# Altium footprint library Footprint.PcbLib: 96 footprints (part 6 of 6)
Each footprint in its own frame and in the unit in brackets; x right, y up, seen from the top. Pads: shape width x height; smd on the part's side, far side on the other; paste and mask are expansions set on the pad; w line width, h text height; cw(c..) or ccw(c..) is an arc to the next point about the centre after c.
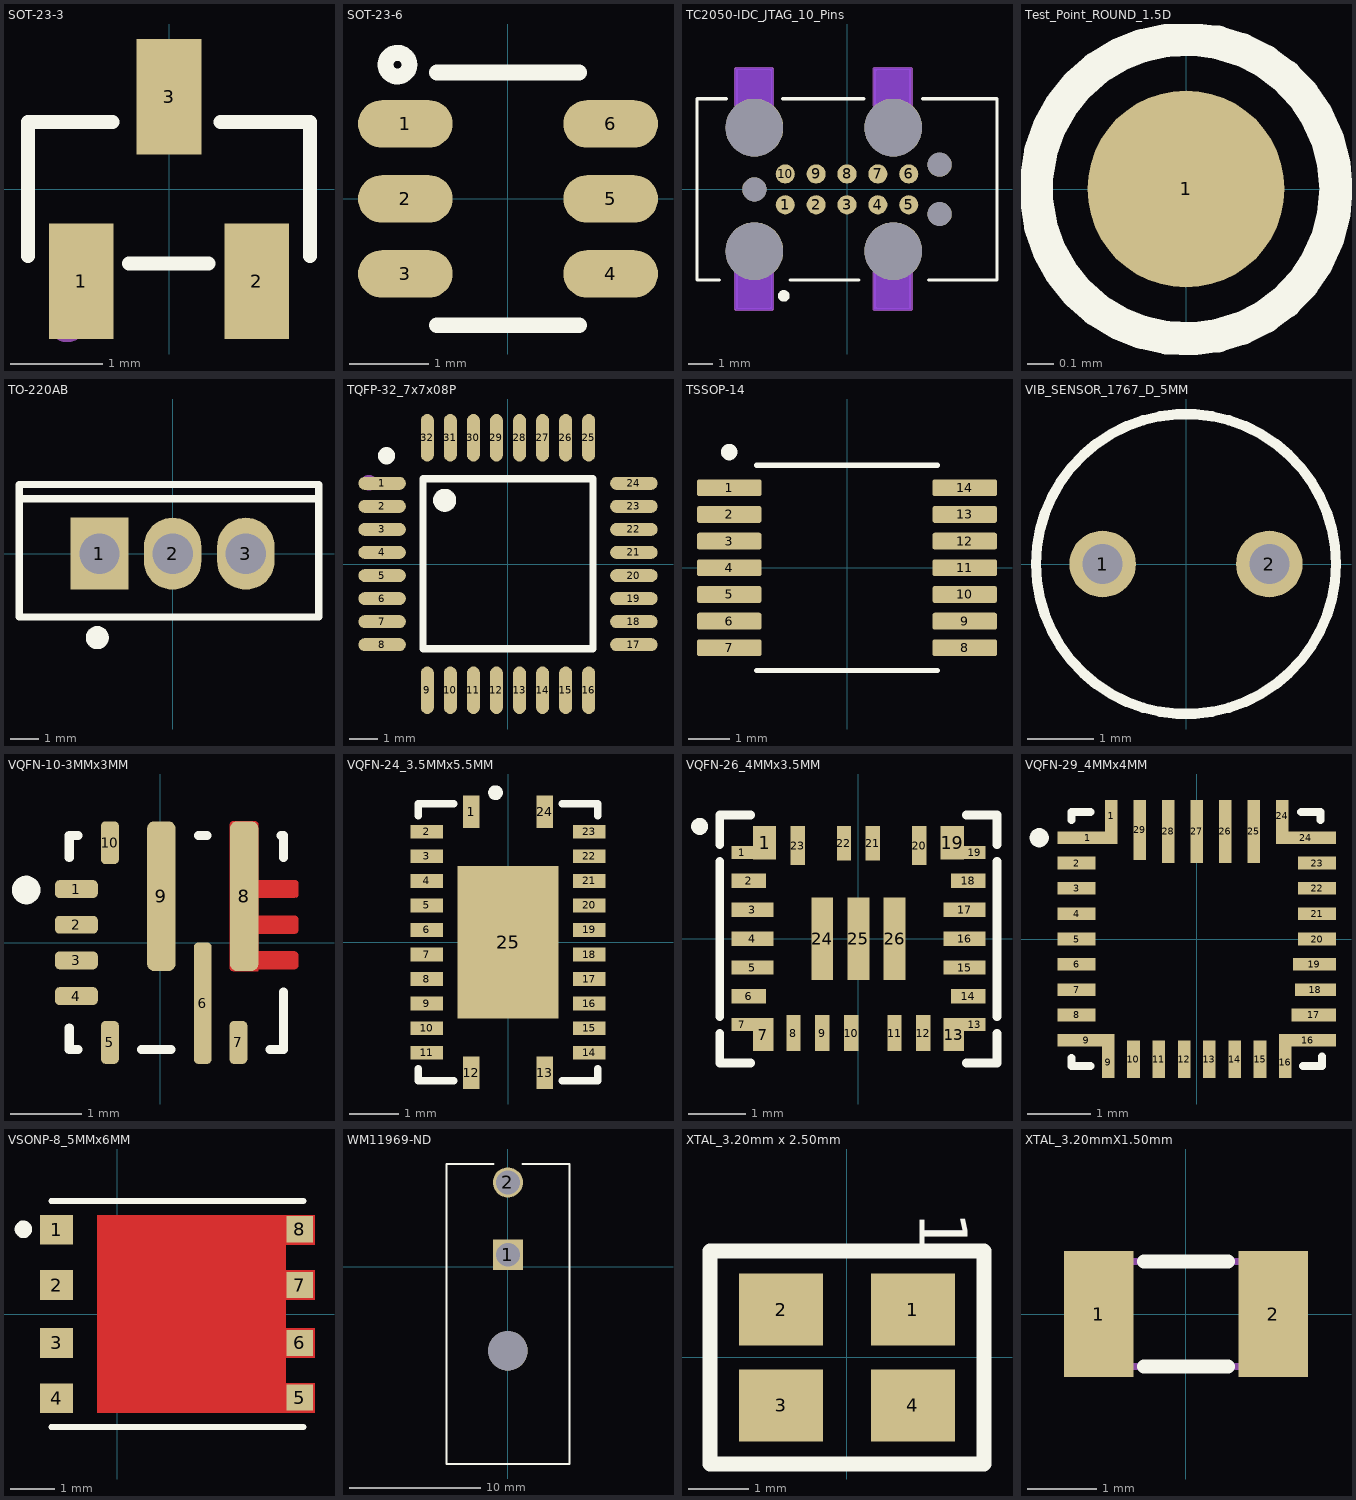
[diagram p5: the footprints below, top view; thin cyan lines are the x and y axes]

## SOT-23-3 [mm]
pads (3):
  rect 0.7x1.25 smd paste+0 mask+0.051: 1(-0.95,-1) 2(0.95,-1) 3(0,1)
Top Overlay:
  lines w0.152: -1.526,-0.726 -1.526,0.726 -0.612,0.726 ; -0.434,-0.807 0.43,-0.807 ; 0.557,0.726 1.526,0.726 1.526,-0.726
Mechanical 15:
  circle w0.2: c-1.1,-1.46 r0.1
3D body "CircuitWorks-SOT-23.step": height 1.1, standoff 0, extent -1.475,-1.326 1.525,1.174

## SOT-23-6 [mm]
pads (6):
  oval 1.2x0.6 smd paste-0.05: 1(-1.3,0.95) 2(-1.3,0) 3(-1.3,-0.95) 4(1.3,-0.95) 5(1.3,0) 6(1.3,0.95)
Top Overlay:
  circle w0.2: c-1.4,1.7 r0.151
  lines w0.2: -0.9,-1.6 0.9,-1.6 ; -0.9,1.6 0.9,1.6
3D body "User Library-SOT23-6.step": height 1.3, standoff 0, extent -1.5,-1.5 1.5,1.5

## TC2050-IDC_JTAG_10_Pins [mil]
pads (17):
  round 31 smd paste-39.37: 1(-100,-25) 2(-50,-25) 3(0,-25) 4(50,-25) 5(100,-25) 6(100,25) 7(50,25) 8(0,25) 9(-50,25) 10(-100,25)
  round 93.5 hole 93.5 unplated: ""(-150,-100) ""(-150,100) ""(75,-100) ""(75,100)
  round 39 hole 39 unplated: ""(-150,0) ""(150,-39.96) ""(150,39.96)
Bottom Layer keep-out:
  region: 44.5,-194.27 103.55,-194.27 103.55,-135.21 44.5,-135.21
  region: -179.91,-194.27 -120.86,-194.27 -120.86,-135.21 -179.91,-135.21
  region: -179.91,136.44 -120.86,136.44 -120.86,195.5 -179.91,195.5
  region: 44.5,136.44 103.55,136.44 103.55,195.5 44.5,195.5
Top Overlay:
  circle w9.45: c-102.36,-172.49 r4.72
  lines w5: -206.69,-146.77 -242.91,-146.77 -242.91,146.77 -194.88,146.77 ; -104.33,146.77 27.56,146.77 ; -92.52,-146.77 19.68,-146.77 ; 122.05,146.77 242.91,146.77 242.91,-146.77 131.89,-146.77
Mechanical 1:
  lines w6: -179.91,-194.27 -179.91,-135.21 -120.86,-135.21 -120.86,-194.27 -179.91,-194.27 ; -179.91,136.44 -179.91,195.5 -120.86,195.5 -120.86,136.44 -179.91,136.44 ; 44.5,-194.27 44.5,-135.21 103.55,-135.21 103.55,-194.27 44.5,-194.27 ; 44.5,136.44 44.5,195.5 103.55,195.5 103.55,136.44 44.5,136.44
3D body "TAG_CONNECT_TC2050-IDC.STEP": height 1152.76, standoff -117.87, extent -242.63,-165.67 247.37,162.92

## Test_Point_ROUND_1.5D [mm]
pads (1):
  round 0.75 smd paste-1: 1(0,0)
Top Overlay:
  circle w0.127: c0,0 r0.571

## TO-220AB [mm]
pads (3):
  rect 2x2.5 hole 1.4 paste+0 mask+0.051: 1(-2.54,0)
  oval 2x2.5 hole 1.4 paste+0 mask+0.051: 2(0,0) 3(2.54,0)
Top Overlay:
  lines w0.254: -5.334,1.905 5.08,1.905 ; -5.327,-2.2 -5.327,2.4 5.073,2.4 5.073,-2.2 -5.327,-2.2
  lines w0.4: -2.617,-2.715 ccw(c-2.616,-2.915) -2.615,-2.715
3D body "TO-220.step": height 19, standoff -4.1, extent -5.1,-1.499 5.1,2.951

## TQFP-32_7x7x08P [mm]
pads (32):
  oval 1.65x0.45 smd: 1(-4.369,2.8) 2(-4.369,2) 3(-4.369,1.2) 4(-4.369,0.4) 5(-4.369,-0.4) 6(-4.369,-1.2) 7(-4.369,-2) 8(-4.369,-2.8) 17(4.369,-2.8) 18(4.369,-2) 19(4.369,-1.2) 20(4.369,-0.4) 21(4.369,0.4) 22(4.369,1.2) 23(4.369,2) 24(4.369,2.8)
  oval 0.45x1.65 smd: 9(-2.8,-4.381) 10(-2,-4.381) 11(-1.2,-4.381) 12(-0.4,-4.381) 13(0.4,-4.381) 14(1.2,-4.381) 15(2,-4.381) 16(2.8,-4.381) 25(2.8,4.382) 26(2,4.382) 27(1.2,4.382) 28(0.4,4.382) 29(-0.4,4.382) 30(-1.2,4.382) 31(-2,4.382) 32(-2.8,4.382)
Top Overlay:
  lines w0.254: -2.95,-2.937 -2.95,2.963 2.95,2.963 2.95,-2.937 -2.95,-2.937
  lines w0.3: -4.064,3.757 cw(c-4.214,3.758) -4.064,3.759
  lines w0.4: -1.999,2.21 cw(c-2.199,2.211) -1.999,2.212
Mechanical 15:
  circle w0.254: c-4.826,2.819 r0.127
  lines w0.254: -4.826,2.671 ccw(c-4.826,2.819) -4.826,2.967 ccw(c-4.826,2.819) -4.826,2.671
3D body "TQFP-32_7x7x08P.stp": height 1.1, standoff 0, extent -4.542,-4.475 4.458,4.525

## TSSOP-14 [mm]
pads (14):
  rrect25% 1.57x0.41 smd mask+0.04: 1(-2.87,1.95) 2(-2.87,1.3) 3(-2.87,0.65) 4(-2.87,0) 5(-2.87,-0.65) 6(-2.87,-1.3) 7(-2.87,-1.95) 8(2.87,-1.95) 9(2.87,-1.3) 10(2.87,-0.65) 11(2.87,0) 12(2.87,0.65) 13(2.87,1.3) 14(2.87,1.95)
Top Overlay:
  circle w0.2: c-2.87,2.819 r0.1
  lines w0.127: -2.2,-2.5 2.2,-2.5 ; -2.2,2.5 2.2,2.5
3D body "step_temp.STEP": height 1.2, standoff 0, extent -3.2,-2.5 3.2,2.5

## VIB_SENSOR_1767_D_5MM [mm]
pads (2):
  round 1 hole 0.6 paste+0 mask+0.051: 1(-1.25,0) 2(1.25,0)
Top Overlay:
  circle w0.152: c0,0 r2.25

## VQFN-10-3MMx3MM [mm]
pads (10):
  rrect50% 0.6x0.25 smd: 1(-1.175,0.75) 2(-1.175,0.25) 3(-1.175,-0.25) 4(-1.175,-0.75)
  rrect50% 0.25x0.6 smd: 5(-0.705,-1.4) 7(1.095,-1.4) 10(-0.705,1.4)
  rrect50% 0.25x1.7 smd paste-2: 6(0.595,-0.85)
  rrect50% 0.4x2.1 smd paste-2 mask+0: 8(1.175,0.65)
  rrect50% 0.4x2.1 smd paste-2: 9(0.015,0.65)
Top Layer:
  region: 286 vertices and 0 holes, not listed, extent 0.975,-0.4 1.936,1.7
Top Overlay:
  circle w0.2: c-1.88,0.737 r0.1
  lines w0.127: -1.275,-1.195 -1.275,-1.5 -1.15,-1.5 ; -1.275,1.195 -1.275,1.5 -1.15,1.5 ; -0.26,-1.5 0.15,-1.5 ; 0.535,1.5 0.655,1.5 ; 1.54,-1.5 1.725,-1.5 1.725,-0.695 ; 1.695,1.5 1.725,1.5 1.725,1.195
Top Solder:
  drawing of 1 lines, arcs and shapes, not listed
3D body "TPS56637RPAR.step": height 1, standoff 0, extent -1.271,-1.5 1.729,1.5

## VQFN-24_3.5MMx5.5MM [mm]
pads (25):
  rect 0.336x0.665 smd paste+0 mask+0.051: 1(-0.75,2.658) 12(-0.75,-2.658) 13(0.75,-2.658) 24(0.75,2.658)
  rect 0.665x0.28 smd paste+0 mask+0.051: 2(-1.658,2.25) 3(-1.658,1.75) 4(-1.658,1.25) 5(-1.658,0.75) 6(-1.658,0.25) 7(-1.658,-0.25) 8(-1.658,-0.75) 9(-1.658,-1.25) 10(-1.658,-1.75) 11(-1.658,-2.25) 14(1.658,-2.25) 15(1.658,-1.75) 16(1.658,-1.25) 17(1.658,-0.75) 18(1.658,-0.25) 19(1.658,0.25) 20(1.658,0.75) 21(1.658,1.25) 22(1.658,1.75) 23(1.658,2.25)
  rect 2.05x3.1 smd paste+0 mask+0.051: 25(0,0)
Top Overlay:
  circle w0.15: c-0.254,3.048 r0.075
  lines w0.152: -1.826,-2.58 -1.826,-2.826 -1.109,-2.826 ; -1.826,2.58 -1.826,2.826 -1.109,2.826 ; 1.109,-2.826 1.826,-2.826 1.826,-2.58 ; 1.109,2.826 1.826,2.826 1.826,2.58
3D body "VQFN-24_L5.5-W3.5-H1.0-P0.50.step": height 1, standoff -0.02, extent -1.76,-2.76 1.76,2.76

## VQFN-26_4MMx3.5MM [mm]
pads (30):
  rect 0.375x0.225 smd mask+0.04: 1(-2.012,1.488) 7(-2.012,-1.488) 13(2.012,-1.488) 19(2.012,1.488)
  rect 0.4x0.575 smd mask+0.04: 1(-1.625,1.662) 19(1.625,1.662)
  rect 0.6x0.25 smd mask+0.04: 2(-1.9,1) 6(-1.9,-1) 14(1.9,-1) 18(1.9,1)
  rect 0.725x0.25 smd mask+0.04: 3(-1.837,0.5) 4(-1.837,0) 5(-1.837,-0.5) 15(1.838,-0.5) 16(1.838,0) 17(1.838,0.5)
  rect 0.35x0.575 smd mask+0.04: 7(-1.65,-1.662) 13(1.65,-1.662)
  rect 0.25x0.625 smd mask+0.04: 8(-1.125,-1.637) 9(-0.625,-1.637) 10(-0.125,-1.637) 11(0.625,-1.637) 12(1.125,-1.637)
  rect 0.25x0.675 smd mask+0.04: 20(1.05,1.613) 23(-1.05,1.613)
  rect 0.25x0.6 smd mask+0.04: 21(0.25,1.65) 22(-0.25,1.65)
  rect 0.375x1.425 smd mask+0.04: 24(-0.625,0) 25(0,0) 26(0.625,0)
Top Overlay:
  circle w0.2: c-2.75,1.944 r0.046
  lines w0.152: -2.4,-1.642 -2.4,-2.156 -1.87,-2.156 ; -2.4,-1.351 -2.4,1.338 ; -2.4,1.629 -2.4,2.144 -1.87,2.144 ; 1.869,-2.156 2.4,-2.156 2.4,-1.641 ; 1.87,2.144 2.4,2.144 2.4,1.629 ; 2.4,-1.351 2.4,1.338
3D body "TPS552882RPMR.STEP": height 1, standoff 0, extent -2,-1.75 2,1.75

## VQFN-29_4MMx4MM [mm]
pads (33):
  rect 0.95x0.2 smd mask+0.041: 1(-1.725,1.6) 24(1.725,1.6)
  rect 0.2x0.5 smd mask+0.041: 1(-1.35,1.95) 9(-1.4,-1.95) 16(1.4,-1.95) 24(1.35,1.95)
  rect 0.6x0.2 smd mask+0.041: 2(-1.9,1.2) 3(-1.9,0.8) 4(-1.9,0.4) 5(-1.9,0) 6(-1.9,-0.4) 7(-1.9,-0.8) 8(-1.9,-1.2) 20(1.9,0) 21(1.9,0.4) 22(1.9,0.8) 23(1.9,1.2)
  rect 0.9x0.2 smd mask+0.041: 9(-1.75,-1.6) 16(1.75,-1.6)
  rect 0.2x0.6 smd mask+0.041: 10(-1,-1.9) 11(-0.6,-1.9) 12(-0.2,-1.9) 13(0.2,-1.9) 14(0.6,-1.9) 15(1,-1.9)
  rect 0.7x0.2 smd mask+0.041: 17(1.85,-1.2)
  rect 0.65x0.2 smd mask+0.041: 18(1.875,-0.8)
  rect 0.68x0.2 smd mask+0.041: 19(1.86,-0.4)
  rect 0.2x1 smd mask+0.041: 25(0.9,1.7) 26(0.45,1.7) 27(0,1.7) 28(-0.45,1.7)
  rect 0.2x0.95 smd mask+0.041: 29(-0.9,1.725)
Top Overlay:
  circle w0.2: c-2.489,1.6 r0.051
  lines w0.127: -1.981,-1.88 -1.981,-2.007 -1.676,-2.007 ; -1.981,1.88 -1.981,2.007 -1.676,2.007 ; 1.651,2.007 1.956,2.007 1.956,1.88 ; 1.676,-2.007 1.981,-2.007 1.981,-1.854
3D body "BQ25672RQMR.step": height 1, standoff 0, extent -2,-2 2,2

## VSONP-8_5MMx6MM [mm]
pads (8):
  rect 0.75x0.675 smd paste-1: 1(-1.376,1.918) 2(-1.376,0.66) 3(-1.376,-0.66) 4(-1.376,-1.917)
  rect 0.6x0.6 smd paste-1 mask+0: 5(4.166,-1.905) 6(4.166,-0.66) 7(4.166,0.66) 8(4.166,1.93)
Top Layer:
  region: 4.504,1.58 3.849,1.58 3.849,0.998 4.504,0.998 4.504,0.323 3.849,0.323 3.849,-0.322 4.504,-0.322 4.504,-0.997 3.849,-0.997 3.849,-1.58 4.504,-1.58 4.504,-2.255 -0.446,-2.255 -0.446,2.255 4.504,2.255
Top Overlay:
  circle w0.2: c-2.134,1.93 r0.1
  lines w0.127: -1.499,-2.575 4.251,-2.575 ; -1.499,2.575 4.251,2.575
Top Solder:
  region: 4.604,1.48 3.949,1.48 3.949,1.098 4.604,1.098 4.604,0.223 3.949,0.223 3.949,-0.222 4.604,-0.222 4.604,-1.097 3.949,-1.097 3.949,-1.48 4.604,-1.48 4.604,-2.355 -0.546,-2.355 -0.546,2.355 4.604,2.355
3D body "PQFN-8_L5.8-W4.9-H1.0-P1.27-LS6.0-BL.step": height 1.04, standoff 0, extent -1.727,-2.488 4.298,2.487

## WM11969-ND [mm]
pads (3):
  rect 2.3x2.3 / inner round 2.3 / far side rect 2.3x2.3 hole 1.8 mask+0.076: 1(0,0.9)
  round 2.3 hole 1.8 mask+0.076: 2(0,6.4)
  round 3 hole 3 unplated mask+0.076: ""(0,-6.4)
Top Overlay:
  lines w0.127: -1.1,7.8 -4.67,7.8 -4.67,-15 4.68,-15 4.68,7.8 1.1,7.8
3D body "768250002.step": height 15.25, standoff -2.88, extent -4.158,-14.977 4.191,6.985

## XTAL_3.20mm x 2.50mm [mm]
pads (4):
  rect 1.4x1.2 smd mask+0.05: 1(1.1,0.8) 2(-1.1,0.8) 3(-1.1,-0.8) 4(1.1,-0.8)
Top Overlay:
  lines w0.254: -2.286,-1.778 2.286,-1.778 2.286,1.778 -2.286,1.778 -2.286,-1.778
  text "1" at 1.216,2.43 h0.8
3D body "SA324320F36MAR.step": height 0.8, standoff 0, extent -1.575,-1.25 1.626,1.25

## XTAL_3.20mmX1.50mm [mm]
pads (2):
  rect 1x1.8 smd: 1(-1.25,0) 2(1.25,0)
Top Overlay:
  lines w0.2: -0.6,-0.75 0.6,-0.75 ; -0.6,0.75 0.6,0.75
Mechanical 7:
  lines w0.1: -1.6,-0.75 1.6,-0.75 1.6,0.75 -1.6,0.75 -1.6,-0.75
Mechanical 15:
  lines w0.1: -1.6,-0.55 cw(c-1.6,-0.75) -1.4,-0.75 1.4,-0.75 cw(c1.6,-0.75) 1.6,-0.55 1.6,0.55 cw(c1.6,0.75) 1.4,0.75 -1.4,0.75 cw(c-1.6,0.75) -1.6,0.55 -1.6,-0.55
3D body "User Library-Siward_SX3215.step": height 0.81, standoff 0, extent -1.6,-0.75 1.6,0.75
